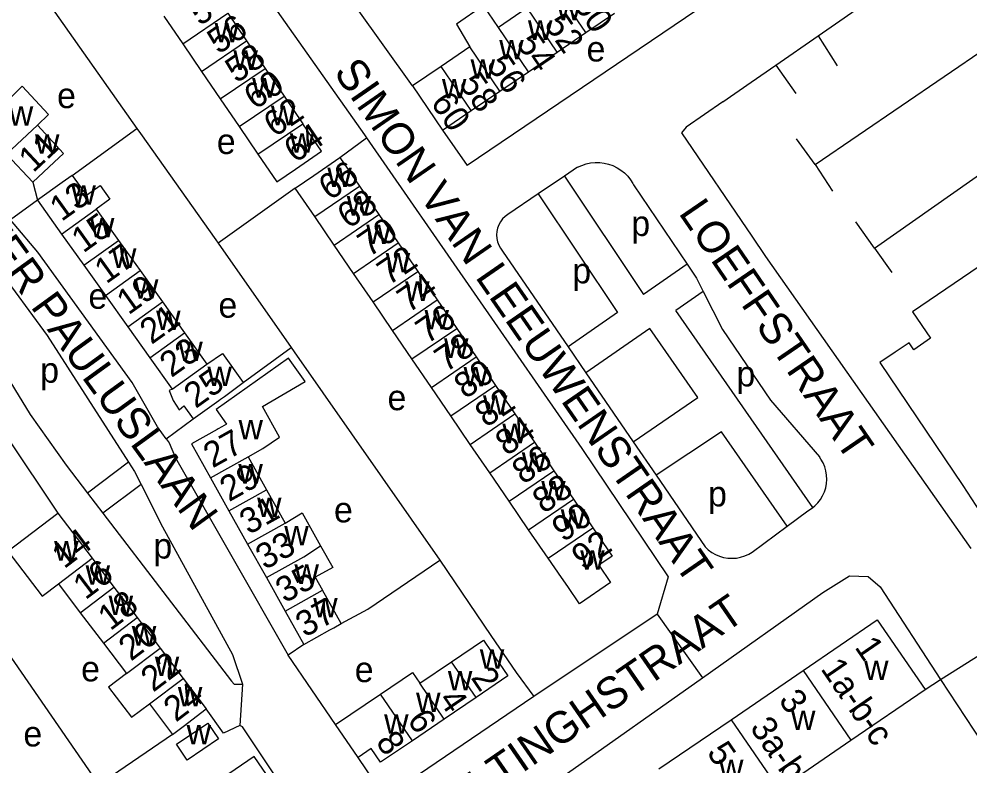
# Model space of a CAD drawing. Extents: x 157569 to 159501, y 382907 to 384670.
# Drawn here: x 158107 to 158257.4, y 383586.2 to 383704.3 of the extents above; entities that cross this region are included whole.
import ezdxf

# ---------------------------------------------------------------- set-up
doc = ezdxf.new("R2010")
doc.units = 0
for name, color, linetype in [('BLT_Basislijn', 7, 'Continuous'), ('BLT_Bebouwing', 7, 'Continuous'), ('BLT_Centroide', 7, 'Continuous'), ('BLT_Huisnummer', 7, 'Continuous'), ('BLT_Huisnummer_ tussenligend', 7, 'Continuous'), ('BLT_Huisnummer_reeks', 7, 'Continuous'), ('BLT_Onderverdeling_panden', 7, 'Continuous'), ('BLT_Straatnaam', 7, 'Continuous'), ('BLT_Vlakafsluiter', 7, 'Continuous')]:
    doc.layers.add(name, color=color, linetype=linetype)

msp = doc.modelspace()

# ---------------------------------------------------------------- linework, layer by layer
at = {"layer": 'BLT_Basislijn'}
for p, q in [((158103.01, 383719.18), (158125.7, 383686.98)), ((158233.4, 383701.65), (158256.76, 383717.85)), ((158169.28, 383693.71), (158160.24, 383706.33)), ((158226.72, 383697.02), (158233.4, 383701.65)), ((158233.4, 383701.65), (158236.41, 383696.91)), ((158232.93, 383681.31), (158260.11, 383699.85)), ((158222.8, 383694.3), (158226.72, 383697.02)), ((158218.34, 383691.2), (158222.8, 383694.3)), ((158115.46, 383679.57), (158125.7, 383686.98)), ((158242.31, 383668.06), (158269.02, 383686.85)), ((158157.8, 383682.38), (158162.01, 383685.51)), ((158174.03, 383686.73), (158177.91, 383681.15)), ((158232.93, 383681.31), (158229.98, 383685.35)), ((158195.38, 383680.86), (158193.3, 383679.46)), ((158232.93, 383681.31), (158235.66, 383677.05)), ((158193.3, 383679.46), (158189.16, 383676.66)), ((158193.3, 383679.46), (158205.8, 383660.76)), ((158109.22, 383678.5), (158109.96, 383675.63)), ((158204.21, 383678.1), (158212.67, 383665.53)), ((158150.73, 383677.55), (158138.52, 383668.83)), ((158189.16, 383676.66), (158184.34, 383673.41)), ((158189.16, 383676.66), (158201.69, 383657.91)), ((158109.96, 383675.63), (158105.68, 383672.52)), ((158242.31, 383668.06), (158239.36, 383672.22)), ((158138.52, 383668.83), (158150.08, 383652.34)), ((158222.92, 383669.96), (158225.1, 383666.74)), ((158183.52, 383667.61), (158193.87, 383652.48)), ((158242.31, 383668.06), (158245.08, 383664.19)), ((158225.1, 383666.74), (158257.54, 383620.55)), ((158212.67, 383665.53), (158205.8, 383660.76)), ((158215.23, 383661.22), (158210.89, 383658.21)), ((158201.69, 383657.91), (158193.87, 383652.48)), ((158232.55, 383627.06), (158210.89, 383658.21)), ((158206.78, 383655.36), (158196.69, 383648.36)), ((158214.37, 383644.45), (158206.78, 383655.36)), ((158142.51, 383646.82), (158150.08, 383652.34)), ((158193.87, 383652.48), (158196.69, 383648.36)), ((158196.69, 383648.36), (158204.16, 383637.45)), ((158204.16, 383637.45), (158214.37, 383644.45)), ((158130.3, 383637.93), (158134.6, 383641.1)), ((158218.15, 383639.01), (158207.79, 383632.14)), ((158228.51, 383624.12), (158218.15, 383639.01)), ((158105.13, 383638.23), (158113.19, 383626.15)), ((158204.16, 383637.45), (158207.79, 383632.14)), ((158124.37, 383634.22), (158117.89, 383629.33)), ((158207.79, 383632.14), (158215.53, 383620.83)), ((158126.35, 383630.7), (158120.32, 383626.15)), ((158117.89, 383629.33), (158120.32, 383626.15)), ((158228.51, 383624.12), (158231.76, 383626.54)), ((158222.98, 383620), (158228.51, 383624.12)), ((158097.37, 383615.52), (158119.69, 383583.19)), ((158152.07, 383605.38), (158149.58, 383603.72)), ((158157.1, 383592.72), (158149.58, 383603.72)), ((158250.31, 383598.27), (158252.74, 383599.87)), ((158252.74, 383599.87), (158260.65, 383587.83)), ((158142.37, 383599.11), (158141.95, 383592.59)), ((158131.34, 383591.17), (158119.69, 383583.19))]:
    msp.add_line(p, q, dxfattribs=at)
for points in [[(158112.56, 383755.26), (158113.42, 383755.44), (158146.58, 383707.38), (158161.69, 383685.98), (158162.01, 383685.51)], [(158219.33, 383717.53), (158223.33, 383711.93), (158177.91, 383681.15)], [(158226.72, 383697.02), (158229.86, 383692.5)], [(158218.34, 383691.2), (158212.52, 383687.22), (158211.81, 383686.29), (158222.92, 383669.96)], [(158125.7, 383686.98), (158126.25, 383686.2), (158138.15, 383669.36), (158138.52, 383668.83)], [(158162.01, 383685.51), (158196.02, 383636.36), (158209.67, 383616.11), (158207.97, 383610.2)], [(158195.38, 383680.86), (158196.04, 383681.16), (158196.72, 383681.39), (158197.43, 383681.54), (158198.14, 383681.61), (158198.87, 383681.6), (158199.58, 383681.52), (158200.28, 383681.35), (158200.96, 383681.11), (158201.61, 383680.79), (158202.22, 383680.4), (158202.78, 383679.95), (158203.29, 383679.44), (158203.74, 383678.88), (158204.12, 383678.27), (158204.21, 383678.1)], [(158184.34, 383673.41), (158183.9, 383673.08), (158183.5, 383672.69), (158183.17, 383672.25), (158182.9, 383671.77), (158182.7, 383671.25), (158182.58, 383670.71), (158182.54, 383670.16), (158182.58, 383669.61), (158182.7, 383669.07), (158182.9, 383668.55), (158183.17, 383668.07), (158183.52, 383667.61)], [(158130.3, 383637.93), (158128.94, 383639.81), (158124.93, 383646.83), (158110.04, 383667.42), (158106.29, 383671.85), (158105.68, 383672.52)], [(158103.5, 383665.1), (158100.11, 383661.84), (158098.82, 383660.19), (158098.87, 383657.98), (158108.79, 383641.74), (158114.49, 383633.77), (158117.89, 383629.33)], [(158103.5, 383665.1), (158111.5, 383654.25), (158124.37, 383634.22)], [(158212.67, 383665.53), (158214.15, 383663.33), (158215.23, 383661.22)], [(158215.23, 383661.22), (158218.29, 383655.19), (158225.88, 383644.01), (158233.61, 383635.05)], [(158150.08, 383652.34), (158150.54, 383651.68), (158173.58, 383618.7)], [(158130.3, 383637.93), (158130.78, 383637.27), (158131.81, 383634.89), (158149.58, 383603.72)], [(158232.55, 383627.06), (158232.87, 383627.31), (158233.34, 383627.79), (158233.76, 383628.33), (158234.11, 383628.91), (158234.39, 383629.52), (158234.6, 383630.17), (158234.72, 383630.83), (158234.77, 383631.5), (158234.74, 383632.18), (158234.63, 383632.85), (158234.44, 383633.5), (158234.18, 383634.12), (158233.85, 383634.71), (158233.61, 383635.05)], [(158124.37, 383634.22), (158125.33, 383632.72), (158126.35, 383630.7)], [(158126.35, 383630.7), (158129.74, 383623.97), (158140.8, 383603.83), (158142.37, 383599.11)], [(158231.76, 383626.54), (158232.34, 383626.89), (158232.55, 383627.06)], [(158120.32, 383626.15), (158140.67, 383599.58), (158141.08, 383599.11), (158142.37, 383599.11)], [(158215.53, 383620.83), (158216.03, 383620.36), (158216.57, 383619.96), (158217.17, 383619.62), (158217.79, 383619.36), (158218.45, 383619.16), (158219.12, 383619.05), (158219.8, 383619.02), (158220.48, 383619.06), (158221.15, 383619.19), (158221.8, 383619.39), (158222.42, 383619.67), (158222.98, 383620)], [(158158, 383608.69), (158162.18, 383610.96), (158173.58, 383618.7)], [(158173.58, 383618.7), (158181.65, 383606.81), (158185.64, 383600.95), (158188.45, 383597.17)], [(158215.11, 383600.13), (158234.13, 383613.61), (158238.35, 383616.24), (158241.29, 383616.16), (158243.21, 383614.51), (158252.74, 383599.87)], [(158207.97, 383610.2), (158188.45, 383597.17)], [(158201.56, 383566.31), (158197.56, 383572.1), (158191.94, 383579.6), (158191.94, 383583.05), (158193.8, 383585.03), (158215.11, 383600.13)], [(158188.45, 383597.17), (158167.4, 383582.89), (158163.23, 383583.78), (158160.66, 383587.51)], [(158141.95, 383592.59), (158139.36, 383591.35), (158136.65, 383595.21)], [(158120.49, 383549.7), (158150.19, 383570.12), (158152.93, 383572.97), (158153.06, 383576.28), (158142.4, 383592.38), (158141.95, 383592.59)]]:
    msp.add_lwpolyline(points, dxfattribs=at)
at = {"layer": 'BLT_Bebouwing'}
for p, q in [((158140.04, 383705.23), (158143.01, 383700.86)), ((158187.4, 383706.04), (158182.87, 383702.96)), ((158196.68, 383702.14), (158201.21, 383705.22)), ((158129.95, 383704.75), (158132.93, 383700.38)), ((158192.15, 383699.05), (158196.68, 383702.14)), ((158132.93, 383700.38), (158135.9, 383696.01)), ((158143.01, 383700.86), (158145.98, 383696.49)), ((158178.34, 383699.88), (158173.81, 383696.79)), ((158187.62, 383695.97), (158192.15, 383699.05)), ((158135.9, 383696.01), (158138.88, 383691.65)), ((158145.98, 383696.49), (158148.96, 383692.11)), ((158173.81, 383696.79), (158169.28, 383693.71)), ((158183.09, 383692.89), (158187.62, 383695.97)), ((158169.28, 383693.71), (158174.03, 383686.73)), ((158178.56, 383689.81), (158183.09, 383692.89)), ((158138.88, 383691.65), (158141.85, 383687.28)), ((158148.96, 383692.11), (158151.93, 383687.74)), ((158174.03, 383686.73), (158178.56, 383689.81)), ((158141.85, 383687.28), (158144.83, 383682.91)), ((158109.22, 383678.5), (158105.07, 383682.94)), ((158157.8, 383682.38), (158160.87, 383677.88)), ((158160.87, 383677.88), (158163.95, 383673.38)), ((158153.81, 383673.05), (158150.73, 383677.55)), ((158109.96, 383675.63), (158113.77, 383670.3)), ((158119.26, 383674.24), (158122.78, 383669.3)), ((158163.95, 383673.38), (158167.02, 383668.88)), ((158156.88, 383668.55), (158153.81, 383673.05)), ((158113.77, 383670.3), (158117.29, 383665.35)), ((158122.78, 383669.3), (158126.2, 383664.51)), ((158167.02, 383668.88), (158170.1, 383664.38)), ((158159.96, 383664.05), (158156.88, 383668.55)), ((158117.29, 383665.35), (158120.71, 383660.56)), ((158126.2, 383664.51), (158129.73, 383659.56)), ((158170.1, 383664.38), (158173.17, 383659.88)), ((158163.03, 383659.55), (158159.96, 383664.05)), ((158120.71, 383660.56), (158124.24, 383655.61)), ((158173.17, 383659.88), (158176.25, 383655.37)), ((158129.73, 383659.56), (158133.21, 383654.66)), ((158166.11, 383655.04), (158163.03, 383659.55)), ((158124.24, 383655.61), (158127.72, 383650.71)), ((158176.25, 383655.37), (158179.32, 383650.87)), ((158133.21, 383654.66), (158136.75, 383649.7)), ((158169.18, 383650.54), (158166.11, 383655.04)), ((158179.32, 383650.87), (158182.4, 383646.37)), ((158127.72, 383650.71), (158131.26, 383645.75)), ((158172.26, 383646.04), (158169.18, 383650.54)), ((158182.4, 383646.37), (158185.47, 383641.87)), ((158175.33, 383641.54), (158172.26, 383646.04)), ((158185.47, 383641.87), (158188.55, 383637.37)), ((158178.41, 383637.04), (158175.33, 383641.54)), ((158188.55, 383637.37), (158191.62, 383632.87)), ((158181.48, 383632.54), (158178.41, 383637.04)), ((158143.27, 383635.05), (158146.17, 383629.85)), ((158191.62, 383632.87), (158194.7, 383628.37)), ((158137.35, 383631.73), (158140.25, 383626.54)), ((158184.56, 383628.04), (158181.48, 383632.54)), ((158146.17, 383629.85), (158149.13, 383624.56)), ((158194.7, 383628.37), (158197.77, 383623.86)), ((158187.63, 383623.54), (158184.56, 383628.04)), ((158140.25, 383626.54), (158143.2, 383621.25)), ((158190.71, 383619.03), (158187.63, 383623.54)), ((158143.2, 383621.25), (158146.16, 383615.96)), ((158118.59, 383619.03), (158122.06, 383614.45)), ((158113.28, 383614.99), (158116.74, 383610.42)), ((158146.16, 383615.96), (158149.12, 383610.67)), ((158122.06, 383614.45), (158125.71, 383609.64)), ((158158, 383608.69), (158155.04, 383613.98)), ((158116.74, 383610.42), (158120.39, 383605.61)), ((158149.12, 383610.67), (158152.07, 383605.38)), ((158125.71, 383609.64), (158129.36, 383604.83)), ((158231.02, 383601.29), (158242.74, 383609.31)), ((158242.74, 383609.31), (158250.31, 383598.27)), ((158120.39, 383605.61), (158124.04, 383600.8)), ((158129.36, 383604.83), (158133.01, 383600.02)), ((158170.42, 383599.25), (158175.45, 383602.67)), ((158219.63, 383593.5), (158231.02, 383601.29)), ((158133.01, 383600.02), (158136.65, 383595.21)), ((158238.6, 383590.25), (158250.31, 383598.27)), ((158179.31, 383596.99), (158174.27, 383593.57)), ((158127.69, 383595.99), (158131.34, 383591.17)), ((158131.95, 383589.62), (158136.89, 383592.95)), ((158136.89, 383592.95), (158138.58, 383590.45)), ((158160.66, 383587.51), (158157.1, 383592.72)), ((158174.27, 383593.57), (158169.24, 383590.15)), ((158208.24, 383585.71), (158219.63, 383593.5)), ((158133.64, 383587.12), (158131.95, 383589.62)), ((158138.58, 383590.45), (158133.64, 383587.12)), ((158227.21, 383582.46), (158238.6, 383590.25))]:
    msp.add_line(p, q, dxfattribs=at)
for points in [[(158182.87, 383702.96), (158180.51, 383706.42), (158176.2, 383703.49), (158178.34, 383699.88)], [(158105.8, 383691.94), (158107.53, 383693.66), (158111.71, 383689.19), (158109.95, 383687.49)], [(158109.95, 383687.49), (158114.1, 383683.05), (158112.6, 383681.66), (158109.22, 383678.5)], [(158144.83, 383682.91), (158147.8, 383678.55), (158150.77, 383680.56), (158154.9, 383683.38), (158151.93, 383687.74)], [(158150.73, 383677.55), (158153.67, 383679.56), (158157.8, 383682.38)], [(158282.74, 383681.4), (158248.33, 383658.02), (158251.19, 383653.83), (158248.52, 383652.01), (158247.78, 383653.1), (158245.6, 383651.61), (158243.18, 383649.96), (158256.29, 383630.54), (158259.72, 383625.26)], [(158115.46, 383679.57), (158113.86, 383678.43), (158109.96, 383675.63)], [(158115.46, 383679.57), (158117.71, 383676.42), (158119.87, 383677.96), (158121.41, 383675.79), (158119.26, 383674.24)], [(158136.75, 383649.7), (158139.23, 383651.39), (158142.51, 383646.82)], [(158143.27, 383635.05), (158145.62, 383636.37), (158148.26, 383638.2), (158145.56, 383643.01), (158152.31, 383646.96), (158149.65, 383650.68), (158138.23, 383642.55), (158139.85, 383640.21), (158139.12, 383639.8), (158138.53, 383639.47), (158138.4, 383639.4), (158134.33, 383637.12), (158137.35, 383631.73)], [(158134.6, 383641.1), (158138.64, 383643.99), (158138.9, 383644.18), (158139.52, 383644.62), (158142.51, 383646.82)], [(158131.26, 383645.75), (158130.81, 383645.57), (158131.43, 383643.96), (158132.36, 383642.5), (158133.13, 383643.13), (158134.6, 383641.1)], [(158105.3, 383620.17), (158113.19, 383626.15)], [(158113.19, 383626.15), (158118.59, 383619.03)], [(158149.13, 383624.56), (158151.83, 383626.19), (158154.74, 383620.98)], [(158197.77, 383623.86), (158200.85, 383619.36), (158198.74, 383617.92), (158200.59, 383615.21), (158195.66, 383611.84), (158193.81, 383614.55), (158192.81, 383615.96), (158190.71, 383619.03)], [(158154.74, 383620.98), (158156.65, 383617.56), (158153.9, 383616.02), (158155.04, 383613.98)], [(158105.3, 383620.17), (158110.71, 383613.03), (158113.28, 383614.99)], [(158152.07, 383605.38), (158156.21, 383607.69), (158156.83, 383608.04), (158158, 383608.69)], [(158175.45, 383602.67), (158180.49, 383606.09), (158181.73, 383604.26), (158184.35, 383600.41), (158179.31, 383596.99)], [(158124.04, 383600.8), (158121.21, 383598.63), (158124.84, 383593.88), (158127.69, 383595.99)], [(158164.21, 383597.55), (158169.29, 383600.96), (158170.42, 383599.25)], [(158157.1, 383592.72), (158164.21, 383597.55)], [(158131.34, 383591.17), (158133, 383592.44), (158136.65, 383595.21)], [(158169.24, 383590.15), (158164.22, 383586.79), (158162.73, 383588.95), (158160.66, 383587.51)], [(158142.43, 383571.82), (158147.43, 383575.24), (158145.8, 383577.42), (158149.52, 383579.96), (158144.23, 383587.69), (158138.2, 383583.56), (158139.5, 383581.66), (158136.97, 383579.93), (158138.64, 383577.36)]]:
    msp.add_lwpolyline(points, dxfattribs=at)
at = {"layer": 'BLT_Onderverdeling_panden'}
for p, q in [((158196.68, 383702.14), (158191.93, 383709.12)), ((158132.93, 383700.38), (158140.04, 383705.23)), ((158192.15, 383699.05), (158187.4, 383706.04)), ((158187.62, 383695.97), (158182.87, 383702.96)), ((158135.9, 383696.01), (158143.01, 383700.86)), ((158183.09, 383692.89), (158178.34, 383699.88)), ((158138.88, 383691.65), (158145.98, 383696.49)), ((158178.56, 383689.81), (158173.81, 383696.79)), ((158141.85, 383687.28), (158148.96, 383692.11)), ((158105.07, 383682.94), (158109.95, 383687.49)), ((158144.83, 383682.91), (158151.93, 383687.74)), ((158153.81, 383673.05), (158160.87, 383677.88)), ((158113.77, 383670.3), (158119.26, 383674.24)), ((158156.88, 383668.55), (158163.95, 383673.38)), ((158117.29, 383665.35), (158122.78, 383669.3)), ((158159.96, 383664.05), (158167.02, 383668.88)), ((158120.71, 383660.56), (158126.2, 383664.51)), ((158163.03, 383659.55), (158170.1, 383664.38)), ((158166.11, 383655.04), (158173.17, 383659.88)), ((158124.24, 383655.61), (158129.73, 383659.56)), ((158169.18, 383650.54), (158176.25, 383655.37)), ((158127.72, 383650.71), (158133.21, 383654.66)), ((158172.26, 383646.04), (158179.32, 383650.87)), ((158131.26, 383645.75), (158136.75, 383649.7)), ((158175.33, 383641.54), (158182.4, 383646.37)), ((158178.41, 383637.04), (158185.47, 383641.87)), ((158181.48, 383632.54), (158188.55, 383637.37)), ((158137.35, 383631.73), (158143.27, 383635.05)), ((158184.56, 383628.04), (158191.62, 383632.87)), ((158140.25, 383626.54), (158146.17, 383629.85)), ((158187.63, 383623.54), (158194.7, 383628.37)), ((158143.2, 383621.25), (158149.13, 383624.56)), ((158190.71, 383619.03), (158197.77, 383623.86)), ((158113.28, 383614.99), (158118.59, 383619.03)), ((158116.74, 383610.42), (158122.06, 383614.45)), ((158149.12, 383610.67), (158155.04, 383613.98)), ((158120.39, 383605.61), (158125.71, 383609.64)), ((158124.04, 383600.8), (158129.36, 383604.83)), ((158179.31, 383596.99), (158175.45, 383602.67)), ((158231.02, 383601.29), (158238.6, 383590.25)), ((158127.69, 383595.99), (158133.01, 383600.02)), ((158174.27, 383593.57), (158170.42, 383599.25)), ((158169.24, 383590.15), (158164.21, 383597.55)), ((158219.63, 383593.5), (158227.21, 383582.46))]:
    msp.add_line(p, q, dxfattribs=at)
msp.add_lwpolyline([(158146.16, 383615.96), (158152.09, 383619.27), (158154.74, 383620.98)], dxfattribs=at)
at = {"layer": 'BLT_Vlakafsluiter'}
for p, q in [((158207.97, 383610.2), (158215.11, 383600.13)), ((158252.74, 383599.87), (158266.09, 383608.24))]:
    msp.add_line(p, q, dxfattribs=at)

# ---------------------------------------------------------------- texts
at = {"layer": 'BLT_Centroide'}
for s, p in [('w', (158192.05, 383704.09)), ('w', (158137.97, 383700.62)), ('w', (158187.52, 383701)), ('w', (158182.98, 383697.92)), ('e', (158196.79, 383697.58)), ('w', (158140.95, 383696.25)), ('w', (158178.45, 383694.84)), ('w', (158143.91, 383691.88)), ('w', (158173.92, 383691.75)), ('e', (158113.07, 383690.21)), ('w', (158105.44, 383687.44)), ('w', (158146.89, 383687.5)), ('w', (158109.58, 383683)), ('e', (158138.33, 383682.95)), ('w', (158149.87, 383683.16)), ('w', (158155.8, 383677.72)), ('w', (158115.34, 383674.94)), ('w', (158158.88, 383673.22)), ('w', (158118.27, 383669.78)), ('p', (158203.86, 383669.99)), ('w', (158161.95, 383668.72)), ('w', (158121.74, 383664.94)), ('w', (158165.03, 383664.22)), ('p', (158194.54, 383662.5)), ('w', (158125.22, 383660.06)), ('w', (158168.1, 383659.72)), ('e', (158118.02, 383658.48)), ('e', (158138.58, 383657.07)), ('w', (158171.17, 383655.22)), ('w', (158128.73, 383655.12)), ('w', (158174.25, 383650.72)), ('w', (158132.24, 383650.22)), ('p', (158110.4, 383646.79)), ('w', (158136.84, 383646.25)), ('w', (158177.33, 383646.22)), ('p', (158220.49, 383646.2)), ('e', (158165.32, 383642.44)), ('w', (158180.41, 383641.72)), ('w', (158141.76, 383637.83)), ('w', (158183.48, 383637.22)), ('w', (158186.55, 383632.69)), ('w', (158141.73, 383630.84)), ('w', (158189.62, 383628.19)), ('p', (158216, 383627.23)), ('w', (158144.69, 383625.56)), ('e', (158156.85, 383624.7)), ('w', (158192.7, 383623.69)), ('w', (158148.99, 383621.06)), ('w', (158112.61, 383618.66)), ('p', (158128.3, 383618.98)), ('w', (158195.78, 383617.22)), ('w', (158117.58, 383614.84)), ('w', (158150.6, 383614.97)), ('w', (158121.22, 383610.03)), ('w', (158153.56, 383609.69)), ('w', (158124.88, 383605.22)), ('w', (158179.91, 383601.55)), ('e', (158116.87, 383599.56)), ('w', (158128.52, 383600.41)), ('w', (158240.67, 383599.78)), ('e', (158160.13, 383599.44)), ('w', (158174.86, 383598.12)), ('w', (158132.17, 383595.59)), ('w', (158169.83, 383594.7)), ('w', (158164.78, 383591.28)), ('w', (158229.12, 383591.88)), ('e', (158107.74, 383589.27)), ('w', (158133.55, 383589.6)), ('w', (158217.73, 383584.09))]:
    msp.add_text(s, height=4, dxfattribs=at).set_placement(p)
at = {"layer": 'BLT_Huisnummer'}
for s, rotation, p in [('54', 34.257, (158135.64, 383703.11)), ('50', 304.2132, (158194.56, 383706.65)), ('54', 304.2132, (158185.55, 383700.49)), ('58', 34.257, (158141.43, 383694.05)), ('60', 304.2132, (158172.02, 383691.08)), ('64', 34.257, (158150.71, 383681.43)), ('11', 43.0395, (158109.29, 383679.88)), ('66', 34.257, (158156.18, 383675.5)), ('13', 35.6023, (158113.76, 383672.18)), ('70', 34.257, (158162.36, 383666.54)), ('17', 35.6023, (158120.84, 383662.31)), ('74', 34.257, (158168.61, 383657.72)), ('21', 35.6023, (158128, 383652.74)), ('78', 34.257, (158174.52, 383648.33)), ('25', 35.6023, (158134.98, 383642.61)), ('82', 34.257, (158180.92, 383639.6)), ('27', 29.2014, (158137.65, 383633.21)), ('86', 34.257, (158186.77, 383630.59)), ('31', 29.2014, (158143.37, 383622.67)), ('14', 37.167, (158114.18, 383617.26)), ('92', 34.257, (158196.2, 383617.06)), ('18', 37.1722, (158121.48, 383607.46)), ('37', 29.2014, (158152.24, 383606.44)), ('2', 304.1831, (158178.4, 383600.14)), ('24', 37.1877, (158131.85, 383593.01)), ('8', 304.1831, (158163.35, 383589.98))]:
    msp.add_text(s, height=4, rotation=rotation, dxfattribs=at).set_placement(p)
at = {"layer": 'BLT_Huisnummer_ tussenligend'}
for s, rotation, p in [('56', 34.257, (158138.59, 383698.62)), ('52', 304.2132, (158189.97, 383703.46)), ('56', 304.2132, (158180.84, 383697.07)), ('60', 34.257, (158144.37, 383689.85)), ('58', 304.2132, (158176.48, 383694.11)), ('62', 34.257, (158147.49, 383685.5)), ('68', 34.257, (158159.13, 383671.02)), ('15', 35.6023, (158117.2, 383667.2)), ('72', 34.257, (158165.46, 383662.06)), ('19', 35.6023, (158124.35, 383657.41)), ('76', 34.257, (158171.55, 383652.81)), ('23', 35.6023, (158131.14, 383647.5)), ('80', 34.257, (158177.6, 383644.12)), ('84', 34.257, (158184.13, 383635.11)), ('29', 29.2014, (158140.25, 383627.88)), ('88', 34.257, (158190, 383625.97)), ('90', 34.257, (158193.08, 383621.48)), ('33', 29.2014, (158145.92, 383617.12)), ('16', 37.167, (158117.55, 383612.35)), ('35', 29.2014, (158149.07, 383611.86)), ('20', 37.1722, (158124.74, 383602.65)), ('22', 37.1722, (158128.26, 383597.75)), ('4', 304.1831, (158173.26, 383596.67)), ('6', 304.1831, (158168.32, 383593.45))]:
    msp.add_text(s, height=4, rotation=rotation, dxfattribs=at).set_placement(p)
at = {"layer": 'BLT_Huisnummer_reeks'}
for s, rotation, p in [('1', 304.4521, (158239.08, 383604.97)), ('1a-b-c', 304.5078, (158233.7, 383601.55)), ('3', 304.4574, (158227.05, 383596.58)), ('3a-b-c-d', 304.5078, (158222.51, 383592.23)), ('5', 304.4548, (158215.7, 383588.3))]:
    msp.add_text(s, height=4, rotation=rotation, dxfattribs=at).set_placement(p)
at = {"layer": 'BLT_Straatnaam'}
for s, height, rotation, p in [('SIMON VAN LEEUWENSTRAAT', 5, 304.683, (158156.68, 383695.88)), ('PIETER PAULUSLAAN', 5, 306, (158093.49, 383679.85)), ('LOEFFSTRAAT', 5, 304.3957, (158211.24, 383673.62)), ('SCHULTINGHSTRAAT', 4.9999, 34.6144, (158164.61, 383569.81))]:
    msp.add_text(s, height=height, rotation=rotation, dxfattribs=at).set_placement(p)

doc.saveas('drawing.dxf')
